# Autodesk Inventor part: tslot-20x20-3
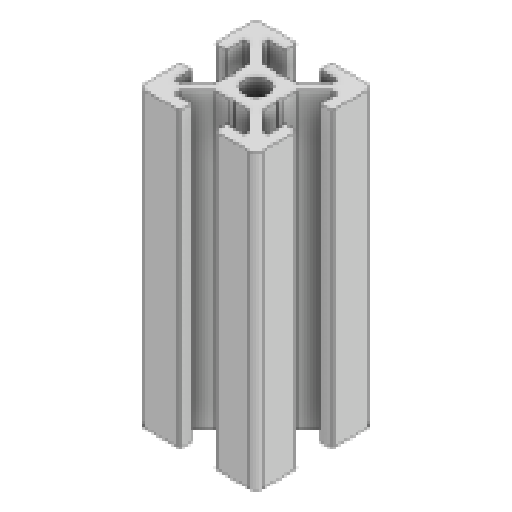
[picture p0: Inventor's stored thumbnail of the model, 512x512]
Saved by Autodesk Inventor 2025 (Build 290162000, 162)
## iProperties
Created: 2025-03
Part Number: tslot-20x20-3
Material: Generico
Document SubType Name: Modeling
Designer: Ryzen5700u
Density: 1 g/cm^3
Appearance: Default
Author: Ryzen5700u
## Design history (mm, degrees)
feature "Base1"
sketch "Schizzo1"
  geometry: L1 (3.761, -16)-(4.7, -16) reference; L2 (3.761, -16)-(0.7, -12.939) reference; L3 (0.7, -12.939)-(0.7, -10.52) reference; L4 (0.4, -10)-(0.7, -10.52) reference; L5 (0.4, -10)-(0.7, -9.48) reference; L6 (0.7, -7.061)-(0.7, -9.48) reference; L7 (3.761, -4)-(0.7, -7.061) reference; L8 (3.761, -4)-(4.7, -4) reference; L9 (4.7, -4)-(4.7, -7) reference; L10 (4.7, -7)-(6.4, -7) reference; L11 (6.7, -6.7)-(6.7, -1) reference; L12 (5.7, 0)-(0, 0) reference; L13 (-0.3, -2)-(-0.3, -0.3) reference; L14 (2.7, -2)-(-0.3, -2) reference; L15 (2.7, -2.939)-(2.7, -2) reference; L16 (2.7, -2.939)-(-0.361, -6) reference; L17 (-0.361, -6)-(-2.78, -6) reference; L18 (-3.3, -6.3)-(-2.78, -6) reference; L19 (-3.3, -6.3)-(-3.82, -6) reference; L20 (-6.239, -6)-(-3.82, -6) reference; L21 (-9.3, -2.939)-(-6.239, -6) reference; L22 (-9.3, -2.939)-(-9.3, -2) reference; L23 (-9.3, -2)-(-6.3, -2) reference; L24 (-6.3, -2)-(-6.3, -0.3) reference; L25 (-12.3, 0)-(-6.6, 0) reference; L26 (-13.3, -6.7)-(-13.3, -1) reference; L27 (-11.3, -7)-(-13, -7) reference; L28 (-11.3, -4)-(-11.3, -7) reference; L29 (-10.361, -4)-(-11.3, -4) reference; L30 (-10.361, -4)-(-7.3, -7.061) reference; L31 (-7.3, -7.061)-(-7.3, -9.48) reference; L32 (-7, -10)-(-7.3, -9.48) reference; L33 (-7, -10)-(-7.3, -10.52) reference; L34 (-7.3, -12.939)-(-7.3, -10.52) reference; L35 (-10.361, -16)-(-7.3, -12.939) reference; L36 (-10.361, -16)-(-11.3, -16) reference; L37 (-11.3, -16)-(-11.3, -13) reference; L38 (-11.3, -13)-(-13, -13) reference; L39 (-13.3, -13.3)-(-13.3, -19) reference; L40 (-12.3, -20)-(-6.6, -20) reference; L41 (-6.3, -18)-(-6.3, -19.7) reference; L42 (-9.3, -18)-(-6.3, -18) reference; L43 (-9.3, -17.061)-(-9.3, -18) reference; L44 (-9.3, -17.061)-(-6.239, -14) reference; L45 (-6.239, -14)-(-3.82, -14) reference; L46 (-3.3, -13.7)-(-3.82, -14) reference; L47 (-3.3, -13.7)-(-2.78, -14) reference; L48 (-0.361, -14)-(-2.78, -14) reference; L49 (2.7, -17.061)-(-0.361, -14) reference; L50 (2.7, -17.061)-(2.7, -18) reference; L51 (2.7, -18)-(-0.3, -18) reference; L52 (-0.3, -18)-(-0.3, -19.7) reference; L53 (5.7, -20)-(0, -20) reference; L54 (6.7, -13.3)-(6.7, -19) reference; L55 (4.7, -13)-(6.4, -13) reference; L56 (4.7, -16)-(4.7, -13) reference; C1 r 2.1 at (-3.3, -10) reference; A1 r 0.3 centre (6.4, -6.7) between (6.4, -7) and (6.7, -6.7) reference; A2 r 1 centre (5.7, -1) between (6.7, -1) and (5.7, 0) reference; A3 r 0.3 centre (0, -0.3) between (0, 0) and (-0.3, -0.3) reference; A4 r 0.3 centre (-6.6, -0.3) between (-6.3, -0.3) and (-6.6, 0) reference; A5 r 1 centre (-12.3, -1) between (-12.3, 0) and (-13.3, -1) reference; A6 r 0.3 centre (-13, -6.7) between (-13.3, -6.7) and (-13, -7) reference; A7 r 0.3 centre (-13, -13.3) between (-13, -13) and (-13.3, -13.3) reference; A8 r 1 centre (-12.3, -19) between (-13.3, -19) and (-12.3, -20) reference; A9 r 0.3 centre (-6.6, -19.7) between (-6.6, -20) and (-6.3, -19.7) reference; A10 r 0.3 centre (0, -19.7) between (-0.3, -19.7) and (0, -20) reference; A11 r 1 centre (5.7, -19) between (5.7, -20) and (6.7, -19) reference; A12 r 0.3 centre (6.4, -13.3) between (6.7, -13.3) and (6.4, -13) reference; 1 further point
extrude "Estrusione1" join sketch "Schizzo1" distance "d0" = 40; taper "d1" = 0 deg
node "Solido1"
node "Linea chiusa proiettata1"
